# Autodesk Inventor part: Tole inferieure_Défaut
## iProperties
Shininess: 64.0
Length Units: 11269
Angle Units: 11279
Time Units: 11290
Mass Units: 11283
Length Display Precision: 3
Angle Display Precision: 2
Compacted: True
Part Number: Tole inferieure_Défaut
Document SubType Name: Modeling
Created: 2006-01
Material: Par défaut
Designer: Fricot
Density: 0.0
Volumn: 0.0
Area: 0.0
PropertySet Name: Model Information
Control State: 0
Master: False
Checked Out: False
Author: Fricot
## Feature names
1. Base1
